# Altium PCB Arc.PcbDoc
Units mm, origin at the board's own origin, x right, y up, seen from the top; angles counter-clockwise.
Board outline 100 x 100 mm, 2 copper layers (Top Layer, Bottom Layer); 32 components, 11 nets, 78 pads, 10 vias.
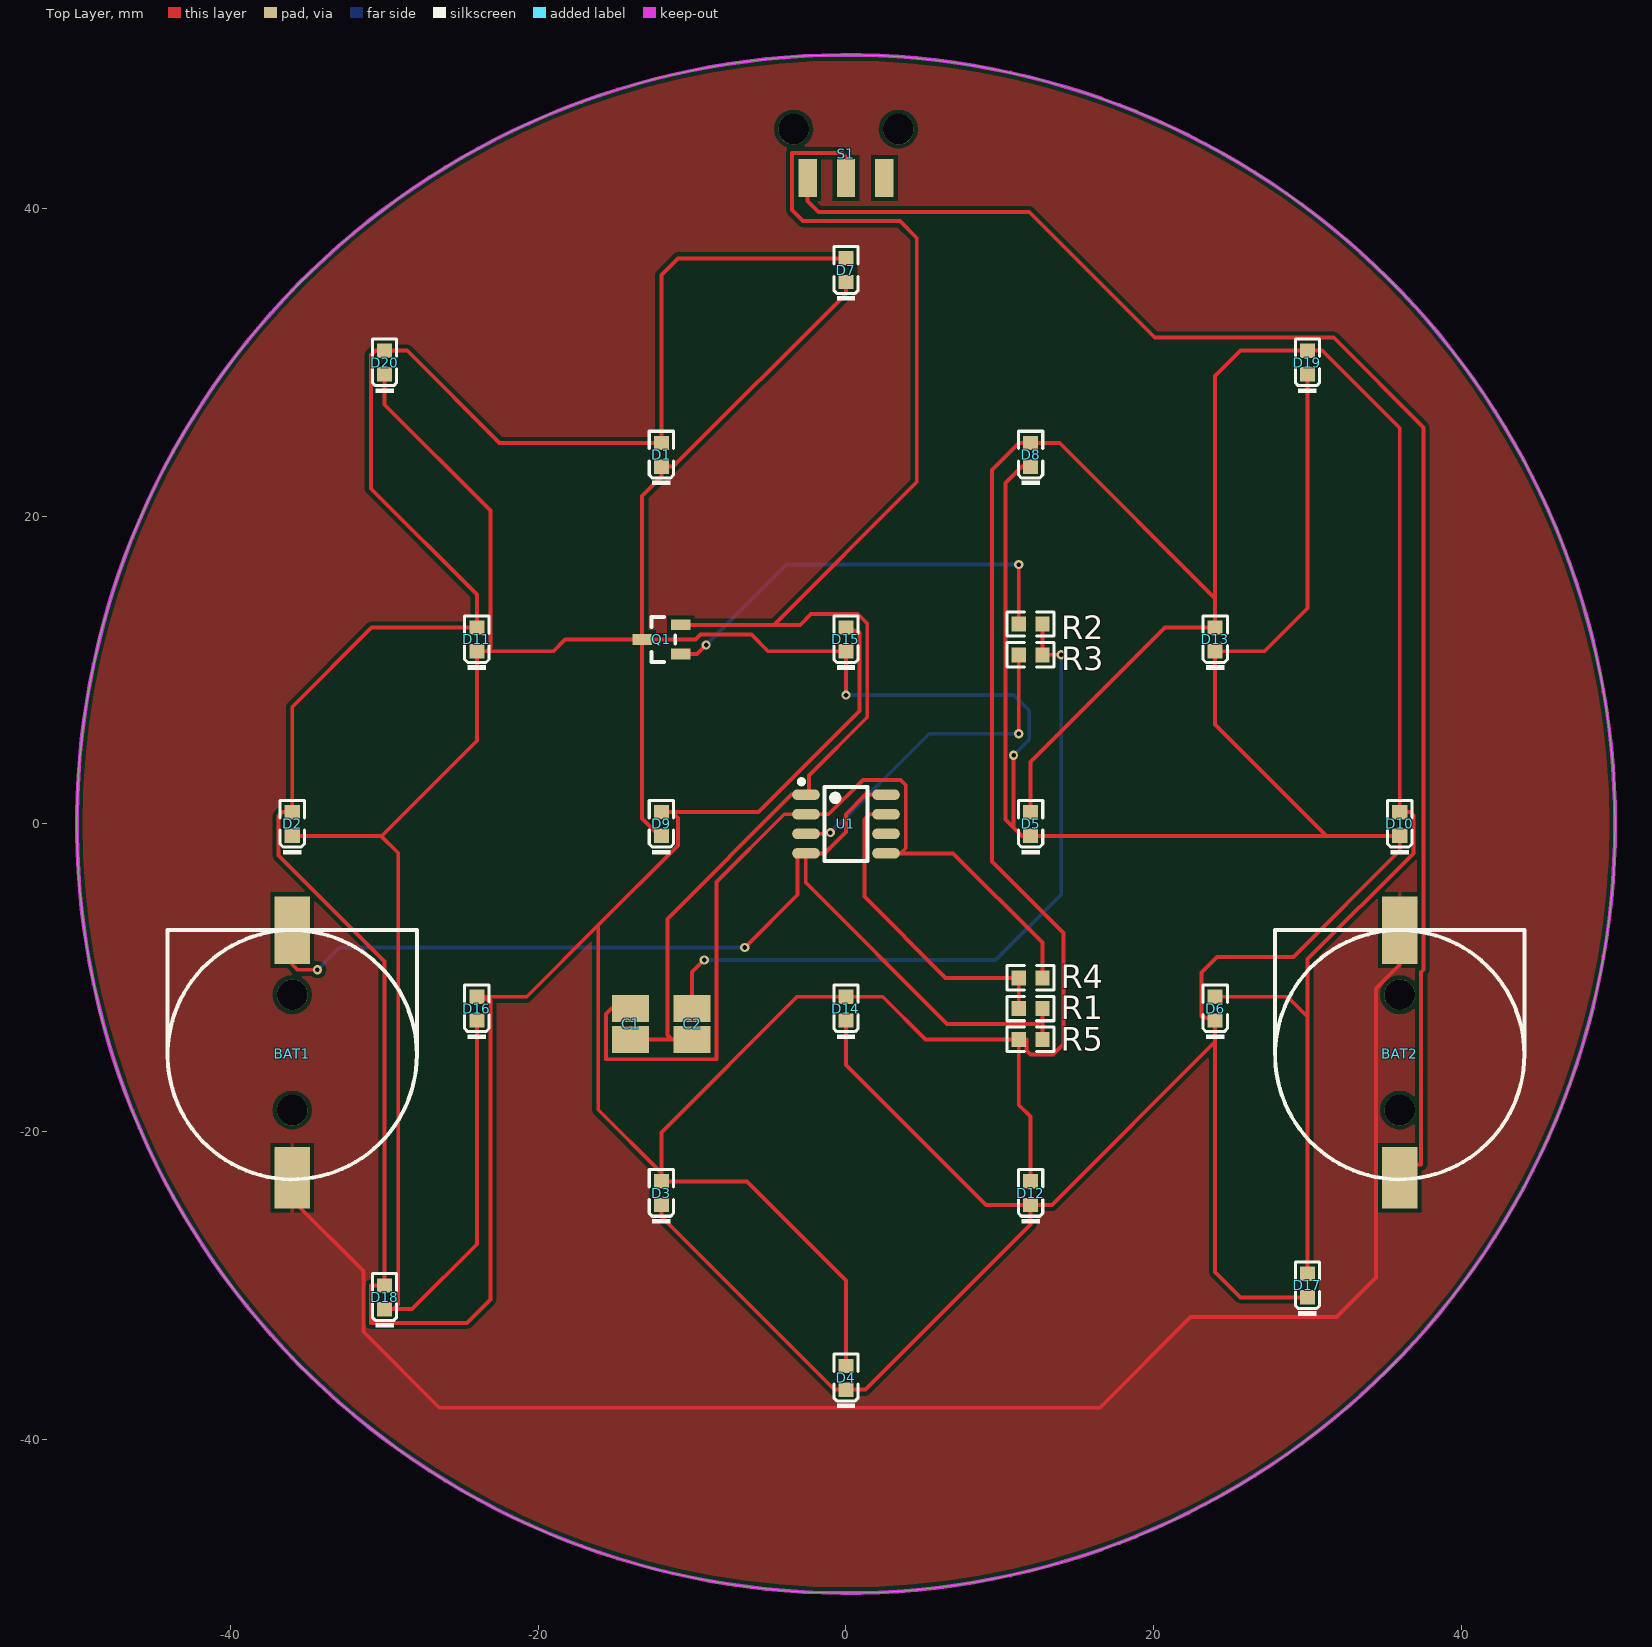
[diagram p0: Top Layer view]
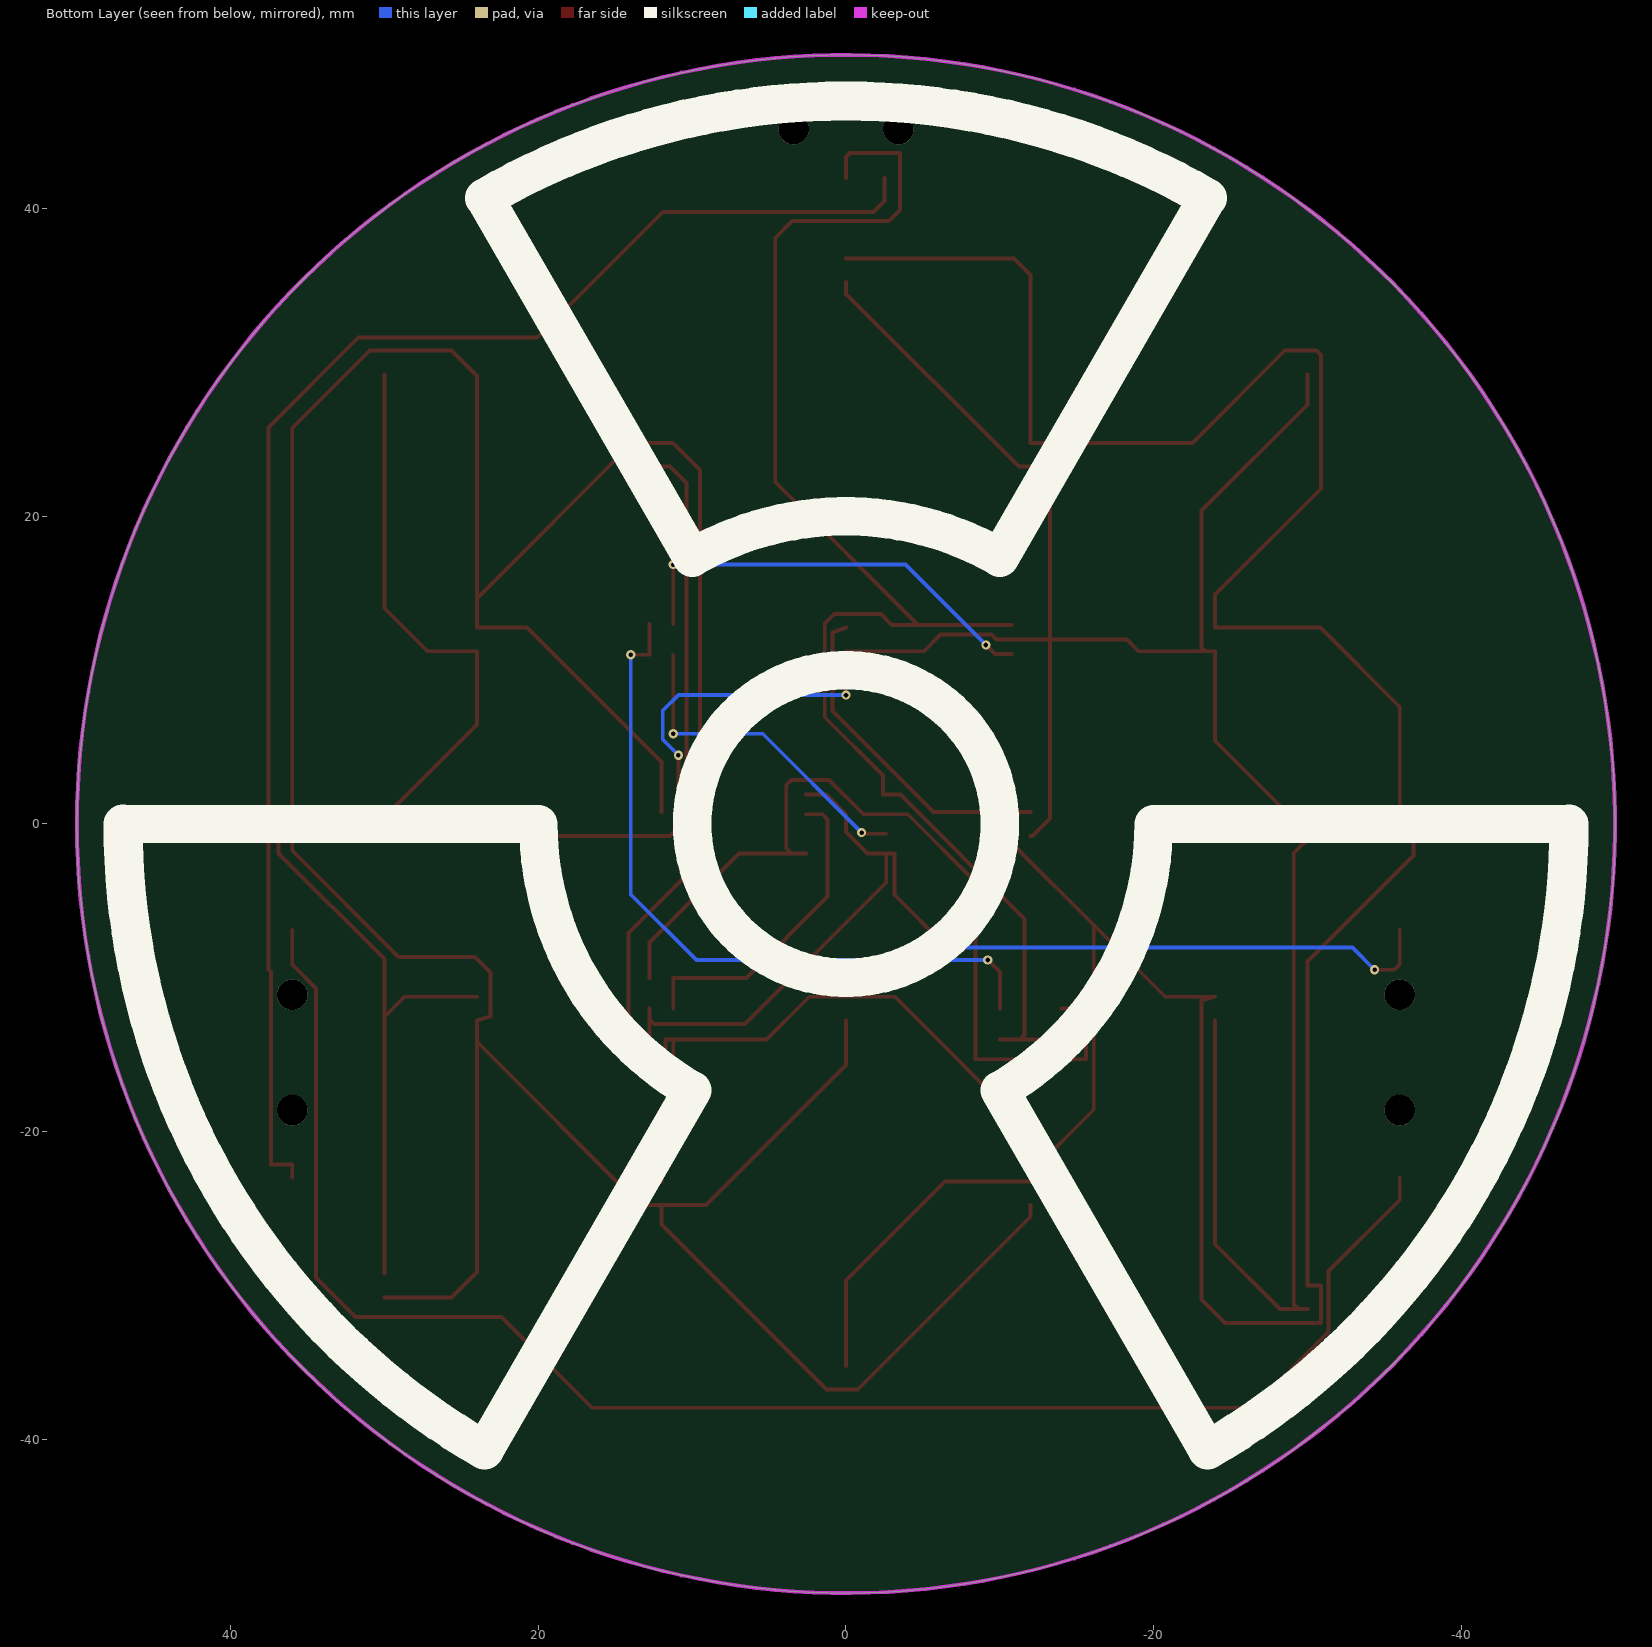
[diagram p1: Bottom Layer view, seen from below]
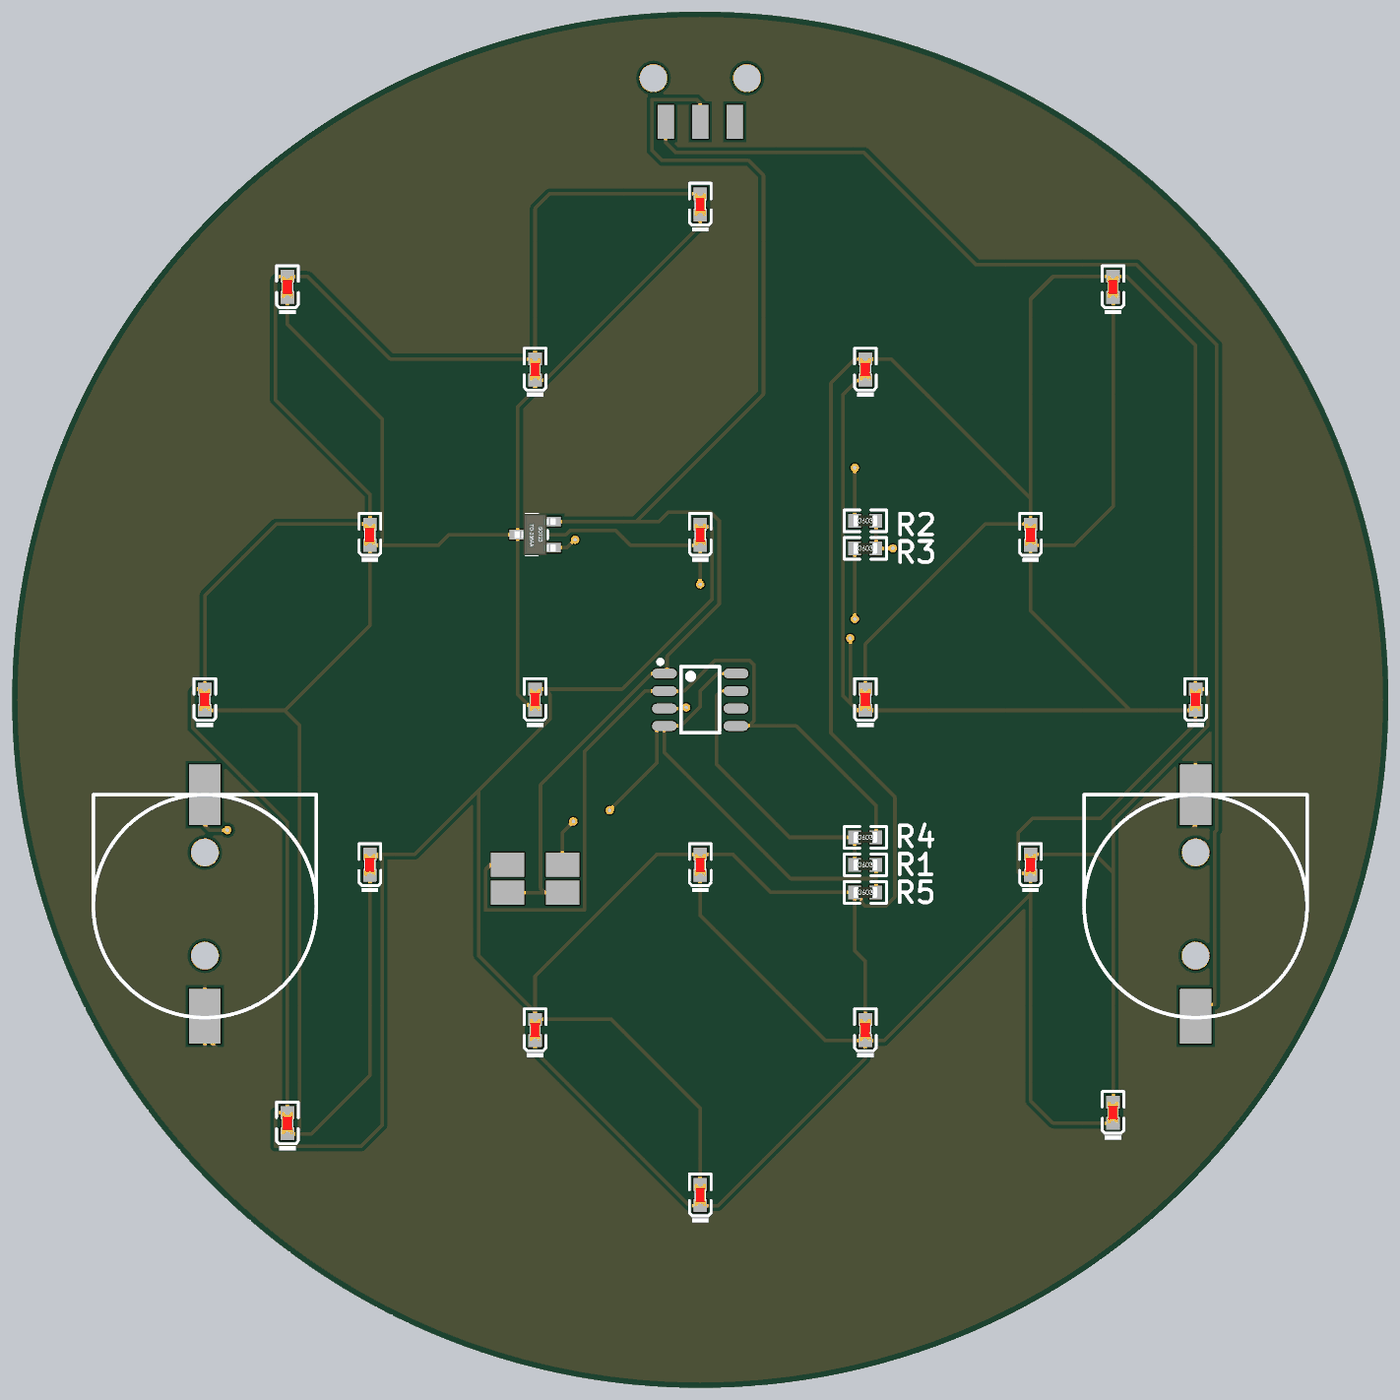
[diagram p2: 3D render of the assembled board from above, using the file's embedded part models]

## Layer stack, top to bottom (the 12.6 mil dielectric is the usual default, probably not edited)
Top Solder: solder mask 0.0102, Solder Resist, Dk 3.5
Top Layer: signal copper 0.0356
Dielectric 1: dielectric 0.32, FR-4, Dk 4.8
Bottom Layer: signal copper 0.0356
Bottom Solder: solder mask 0.0102, Solder Resist, Dk 3.5

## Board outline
-50,0 ccw(c0,0) 0,-50 ccw(c0,0) 50,0 ccw(c0,0) 0,50 ccw(c0,0)

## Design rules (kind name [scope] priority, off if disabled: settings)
Clearance [All] p1: gap=0.254 ignorepadtopadclearanceinfootprint=FALSE except(0: Arc-Hole Track-Hole SMDPad-Hole THPad-Hole Via-Hole Fill-Hole Poly-Hole Region-Hole Text-Hole)
PolygonConnect [All] p1: connectstyle=Relief reliefconductorwidth=0.254 reliefentries=4 polygonreliefangle="90 Angle" airgapwidth=0.254
RoutingVias [All] p1: holewidth=0.3 width=0.6 viastyle="Through Hole" minholewidth=0.3 minwidth=0.6 maxholewidth=0.3 maxwidth=0.6
SolderMaskExpansion [All] p1: expansion=0.102
Width [All] p1: maxlimit=0.254 minlimit=0.254 preferedwidth=0.254
30 further rules are at their usual default settings.

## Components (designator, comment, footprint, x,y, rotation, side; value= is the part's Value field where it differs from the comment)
BAT1 "Power" CR1220_Dock -36,-15 r90 top
BAT2 "Power" CR1220_Dock 36,-15 r90 top
C1 "Cap" *CAPCP3528X210N -14,-13 r270 top
C2 "Cap" *CAPCP3528X210N -10,-13 r270 top
D1 "蓝灯 0603" 0603_LED_S1 -12,24 r90 top
D2 "蓝灯 0603" 0603_LED_S1 -36,0 r90 top
D3 "蓝灯 0603" 0603_LED_S1 -12,-24 r90 top
D4 "蓝灯 0603" 0603_LED_S1 0,-36 r90 top
D5 "蓝灯 0603" 0603_LED_S1 12,0 r90 top
D6 "蓝灯 0603" 0603_LED_S1 24,-12 r90 top
D7 "蓝灯 0603" 0603_LED_S1 0,36 r90 top
D8 "蓝灯 0603" 0603_LED_S1 12,24 r90 top
D9 "蓝灯 0603" 0603_LED_S1 -12,0 r90 top
D10 "蓝灯 0603" 0603_LED_S1 36,0 r90 top
D11 "蓝灯 0603" 0603_LED_S1 -24,12 r90 top
D12 "蓝灯 0603" 0603_LED_S1 12,-24 r90 top
D13 "蓝灯 0603" 0603_LED_S1 24,12 r90 top
D14 "蓝灯 0603" 0603_LED_S1 0,-12 r90 top
D15 "蓝灯 0603" 0603_LED_S1 0,12 r90 top
D16 "蓝灯 0603" 0603_LED_S1 -24,-12 r90 top
D17 "蓝灯 0603" 0603_LED_S1 30,-30 r90 top
D18 "蓝灯 0603" 0603_LED_S1 -30,-30.77 r90 top
D19 "蓝灯 0603" 0603_LED_S1 30,30 r90 top
D20 "蓝灯 0603" 0603_LED_S1 -30,30 r90 top
Q1 "SS8050 Y1" SOT-23(SOT-23-3) -12,12 r0 top
R1 "10KΩ (1002) ±1%" 0603_R 12,-12 r0 top
R2 "10KΩ (1002) ±1%" 0603_R 12,13 r0 top
R3 "47KΩ (4702) ±1%" 0603_R 12,11 r0 top
R4 "47KΩ (4702) ±1%" 0603_R 12,-10 r0 top
R5 "1.6k" 0603_R 12,-14 r0 top
S1 "SW-SPDT" sw_9*3.5*5.5mm 0,42 r0 top
U1 "NE555DR" SOIC-8_150mil 0,0 r270 top

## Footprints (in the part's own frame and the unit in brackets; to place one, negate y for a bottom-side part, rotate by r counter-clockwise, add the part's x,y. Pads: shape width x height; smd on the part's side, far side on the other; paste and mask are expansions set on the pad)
0603_LED_S1 [mm]
  rect 0.93x0.98 smd: A(0.77,0) K(-0.77,0)
  silkscreen extent -1.97,-0.79 1.54,0.79, body extent -0.8,-0.4 0.8,0.4, height 0.6
0603_R [mm]
  rect 0.93x0.98 smd: 1(-0.77,0) 2(0.77,0)
  silkscreen extent -1.53,-0.79 1.54,0.79, body extent -0.85,-0.4 0.85,0.4, height 0.56
*CAPCP3528X210N [mil]
  rect 69x95 smd: 1(-40,0) 2(40,0)
CR1220_Dock [mm]
  round 2 hole 2: 0(-3.6,0) 0(3.9,0)
  rect 4.4x2.3 smd mask+0.102: +(8.1,0)
  rect 4x2.3 smd mask+0.102: -(-8,0)
  silkscreen extent -8.1,-8.1 8.1,8.1
SOIC-8_150mil [mm]
  oval 0.7x1.8 smd: 1(-1.905,-2.6) 2(-0.635,-2.6) 3(0.635,-2.6) 4(1.905,-2.6) 5(1.905,2.6) 6(0.635,2.6) 7(-0.635,2.6) 8(-1.905,2.6)
  silkscreen extent -2.9,-3.05 2.4,1.4
SOT-23(SOT-23-3) [mm]
  rect 1.25x0.7 smd: 1(1.25,-0.95) 2(1.25,0.95) 3(-1.25,0)
  silkscreen extent -0.65,-1.46 0.9,1.46, body extent -1.5,-1.5 1.5,1.5, height 1.3
sw_9*3.5*5.5mm [mm]
  rect 1.2x2.45 smd: 1(-2.5,0) 2(0,0) 3(2.5,0)
  round 2 hole 2: 4(-3.4,3.175) 4(3.4,3.175)
  Top Layer pour cut-out: -1.5,7.9

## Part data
D1 D2 D3 D4 D5 D6 D7 D8 D9 D10 D11 D12 D13 D14 D15 D16 D17 D18 D19 D20: library part "0603 蓝灯", "发光二极管", Package=0603, SuppliersPartNumber=C72041
Q1: library part "SOT-23 SS8050 Y1", "三极管", Package=SOT-23, SuppliersPartNumber=C2150
R1 R2: library part "0603 10KΩ (1002) 1%", "贴片电阻", Package=0603, SuppliersPartNumber=C25804
R3 R4: library part "0603 47KΩ (4702) 1%", "贴片电阻", Package=0603, SuppliersPartNumber=C25819
R5: library part "0603 1.2KΩ (1201) 1%", "贴片电阻", Package=0603, SuppliersPartNumber=C22765
S1: "SPDT Subminiature Toggle Switch, Right Angle Mounting, Vertical Actuation"
U1: library part NE555DR_[C7593], "时基集成", Package=SOIC-8_150mil, SuppliersPartNumber=C7593

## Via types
v1: diameter 0.6, hole 0.3, Top Layer to Bottom Layer, 10 vias

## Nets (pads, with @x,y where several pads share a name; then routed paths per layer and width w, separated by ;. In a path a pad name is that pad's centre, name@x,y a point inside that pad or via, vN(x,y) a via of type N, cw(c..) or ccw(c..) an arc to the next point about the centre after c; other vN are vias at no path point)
NetBAT1_+: BAT1.+ R1.2 R5.2 U1.4 U1.8 | length 71.2
  Top Layer w0.254: BAT1.+ -36,-9.144 -35.67,-9.474 v1(-34.366,-9.474) ; v1(-6.579,-8.026) -3.15,-4.597 -3.15,-1.905 U1.4@-2.616,-1.905 ; U1.8 1.27,1.905 0,0.635 0,-0.508 -1.397,-1.905 U1.4 U1.4@-2.616,-1.905 ; R5.2 12.77,-12.7 ; R1.2 12.77,-12.7 ; U1.4@-2.616,-1.905 -2.616,-3.81 6.579,-13.005 12.465,-13.005 12.77,-12.7
  Bottom Layer w0.254: v1(-34.366,-9.474) -32.918,-8.026 v1(-6.579,-8.026)
NetBAT1_-: BAT1.- BAT2.+ | length 106.5
  Top Layer w0.254: BAT1.- -36,-24.435 -31.379,-29.056 -31.379,-33.01 -26.441,-37.948 16.51,-37.948 22.403,-32.055 31.877,-32.055 34.442,-29.489 34.442,-10.702 36,-9.144 BAT2.+
NetBAT2_-: BAT2.- S1.1 | length 97.9
  Top Layer w0.254: S1.1 -2.5,40.498 -1.778,39.776 11.913,39.776 20.073,31.616 31.706,31.616 37.541,25.781 37.541,-9.474 37.389,-9.627 37.389,-22.149 36,-22.149 BAT2.-
NetC1_+: C1.1 R4.2 U1.2 U1.5 | length 58
  Top Layer w0.254: C1.1 -15.24,-11.984 -15.596,-12.34 -15.596,-15.291 -8.407,-15.291 -8.407,-3.759 -4.013,0.635 U1.2 -1.143,0.635 1.092,2.87 3.556,2.87 3.886,2.54 3.886,-1.575 3.556,-1.905 ; U1.5 3.556,-1.905 ; R4.2 12.77,-7.715 6.96,-1.905 3.556,-1.905
NetC1__: C1.2 C2.2 Q1.2 S1.2 U1.1 | length 96.4
  Top Layer w0.254: C1.2 -11.308,-14.016 ; Q1.2 -4.674,12.95 ; C2.2 -11.308,-14.016 ; S1.2 0,43.358 -0.254,43.612 -3.505,43.612 -3.505,39.903 -2.794,39.192 3.505,39.192 4.597,38.1 4.597,22.221 -4.674,12.95 ; -11.308,-14.016 -11.608,-13.716 -11.608,-6.172 -3.531,1.905 U1.1 -2.413,1.905 -2.413,3.15 1.379,6.942 1.379,13.023 0.762,13.64 -2.286,13.64 -2.976,12.95 -4.674,12.95
NetC2_+: C2.1 R2.2 R3.2 | length 47.3
  Top Layer w0.254: C2.1 -10.008,-11.984 -10.008,-9.627 v1(-9.22,-8.839) ; R2.2 R3.2 v1(13.995,11)
  Bottom Layer w0.254: v1(-9.22,-8.839) 9.728,-8.839 13.995,-4.572 v1(13.995,11)
NetD1_A: D1.A D2.A D3.A D4.A D5.A D6.A D7.A D8.A D9.A D10.A D11.A D12.A D13.A D14.A D15.A D16.A D17.A D18.A D19.A D20.A R5.1 | length 450.5
  Top Layer w0.254: D9.A -11.311,0.77 ; D4.A 0,-29.667 -6.437,-23.23 D3.A -12,-22.682 ; D15.A 0.871,12.446 0.871,7.341 -5.7,0.77 -11.311,0.77 ; D7.A -10.922,36.77 -12,35.692 D1.A -22.524,24.77 -28.524,30.77 D20.A -30.596,30.77 -30.886,30.48 -30.886,21.796 -24,14.91 D11.A -30.836,12.77 -36,7.606 D2.A -36.619,0.77 -36.881,0.508 -36.881,-2.057 -30,-8.938 D18.A -30.871,-30 -30.871,-32.436 -24.638,-32.436 -23.114,-30.912 -23.114,-11.484 D16.A -20.755,-11.23 -16.104,-6.579 ; D12.A 12,-19.025 11.23,-18.255 R5.1 ; D5.A 12,4.044 20.726,12.77 D13.A 24,14.664 ; D6.A 28.702,-11.23 30,-12.528 ; D17.A 30,-12.528 ; -16.104,-6.579 -10.922,-1.397 -10.922,0.381 -11.311,0.77 ; -16.104,-6.579 -16.104,-18.579 -12,-22.682 ; -12,-22.682 -12,-20.052 -3.178,-11.23 D14.A 2.391,-11.23 5.161,-14 R5.1 ; R5.1 11.735,-14 11.735,-14.732 11.989,-14.986 13.462,-14.986 14.148,-14.3 14.148,-7.085 9.5,-2.437 9.5,23.012 11.257,24.77 D8.A 13.894,24.77 24,14.664 ; 24,14.664 24,29.116 25.654,30.77 D19.A 30.963,30.77 36,25.733 D10.A 36.652,0.77 36.881,0.541 36.881,-1.906 30,-8.787 30,-12.528
NetD1_K: D1.K D2.K D3.K D4.K D5.K D6.K D7.K D8.K D9.K D10.K D11.K D12.K D13.K D14.K D15.K D16.K D17.K D18.K D19.K D20.K Q1.3 | length 387.2
  Top Layer w0.254: D2.K -30.226,-0.77 ; D18.K -29.406,-31.54 ; D20.K -30,27.257 -23.114,20.371 -23.114,11.484 -23.368,11.23 ; D16.K -24,-27.321 -28.219,-31.54 -29.406,-31.54 ; D3.K -12,-25.532 -0.762,-36.77 D4.K 1.27,-36.77 12,-26.04 D12.K ; D9.K -12.133,-0.77 -13.259,0.356 Q1.3@-13.259,12 ; D14.K 0,-15.672 9.098,-24.77 D12.K ; v1(0,8.382) D15.K -5.058,11.23 -6.144,12.316 -9.465,12.316 -9.782,12 Q1.3 Q1.3@-13.259,12 ; D7.K 0,34.468 -11.238,23.23 D1.K -12,22.581 -13.259,21.322 Q1.3@-13.259,12 ; v1(10.897,4.47) 10.897,-0.237 ; D8.K 11.43,23.23 10.363,22.163 10.363,0.297 10.897,-0.237 ; D17.K 25.654,-30.77 24,-29.116 24,-14.156 ; D19.K 30,14.023 27.207,11.23 D13.K 24,6.477 31.247,-0.77 ; -30.226,-0.77 -30.18,-0.77 -24,5.41 D11.K -23.368,11.23 ; -30.226,-0.77 -29.108,-1.888 -29.108,-31.242 -29.406,-31.54 ; -23.368,11.23 -19.025,11.23 -18.255,12 Q1.3@-13.259,12 ; 10.897,-0.237 11.43,-0.77 D5.K 31.247,-0.77 ; D12.K 13.386,-24.77 24,-14.156 ; 24,-14.156 D6.K 23.114,-12.516 23.114,-9.652 24.13,-8.636 29.093,-8.636 36,-1.729 D10.K 31.247,-0.77
  Bottom Layer w0.254: v1(0,8.382) 10.897,8.382 11.913,7.366 11.913,5.486 v1(10.897,4.47)
NetQ1_1: Q1.1 R2.1 | length 28.3
  Top Layer w0.254: Q1.1 -9.676,11.05 v1(-9.093,11.633) ; R2.1 v1(11.23,16.866)
  Bottom Layer w0.254: v1(-9.093,11.633) -3.861,16.866 v1(11.23,16.866)
NetR1_1: R1.1 R4.1 U1.7 | length 20.8
  Top Layer w0.254: U1.7 1.524,0.635 1.194,0.305 1.194,-4.724 6.469,-10 R4.1 R1.1
NetR3_1: R3.1 U1.3 | length 21.7
  Top Layer w0.254: U1.3 -1.092,-0.635 v1(-1.016,-0.559) ; v1(11.23,5.867) R3.1
  Bottom Layer w0.254: v1(-1.016,-0.559) 5.41,5.867 v1(11.23,5.867)
pads on no net: BAT1.0 BAT2.0 S1.3 S1.4 U1.6

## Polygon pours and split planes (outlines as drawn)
NetBAT1_- on Top Layer "NETBAT1_-_L01_P000" (solid, remove dead copper, pour order 0): -53.594,57.912 -53.594,54.737 59.563,54.737 59.563,-55.499 -56.769,-55.499

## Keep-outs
Keep-Out Layer:
  circle w0.254: c0,0 r50

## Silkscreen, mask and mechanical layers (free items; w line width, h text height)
Bottom Overlay:
  circle w2.5: c0,0 r10
  lines w2.5: -47,0 -20,0 ccw(c0,0) -10,-17.321 -23.5,-40.703 ; -23.5,40.703 -10,17.321 cw(c0,0) 10,17.321 23.5,40.703 ; 23.5,-40.703 10,-17.321 ccw(c0,0) 20,0 47,0
  lines w2.54: -47,0 ccw(c0,0) -23.5,-40.703 ; -23.5,40.703 cw(c0,0) 23.5,40.703 ; 23.5,-40.703 ccw(c0,0) 47,0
